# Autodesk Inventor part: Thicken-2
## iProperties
Shininess: 64.0
Length Units: 11269
Angle Units: 11279
Time Units: 11290
Mass Units: 11283
Length Display Precision: 3
Angle Display Precision: 2
Compacted: True
Part Number: Thicken-2
Document SubType Name: Modeling
Created: 2003-10
Designer: Owner
Manufacturer: Standard
Standards Organization: Custom
Density: 1 g/cm^3
Density: 0.0
Volumn: 0.0
Area: 0.0
PropertySet Name: Model Information
Control State: 0
Master: False
Checked Out: False
Author: Owner
